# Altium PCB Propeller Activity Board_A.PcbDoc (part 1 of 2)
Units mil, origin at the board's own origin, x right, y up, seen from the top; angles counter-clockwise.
Board outline 4000 x 3050 mil, 4 copper layers (Top Layer, INT1, INT2, Bottom Layer), stack 61.6 mil thick; 104 components, 104 nets, 469 pads, 175 vias.
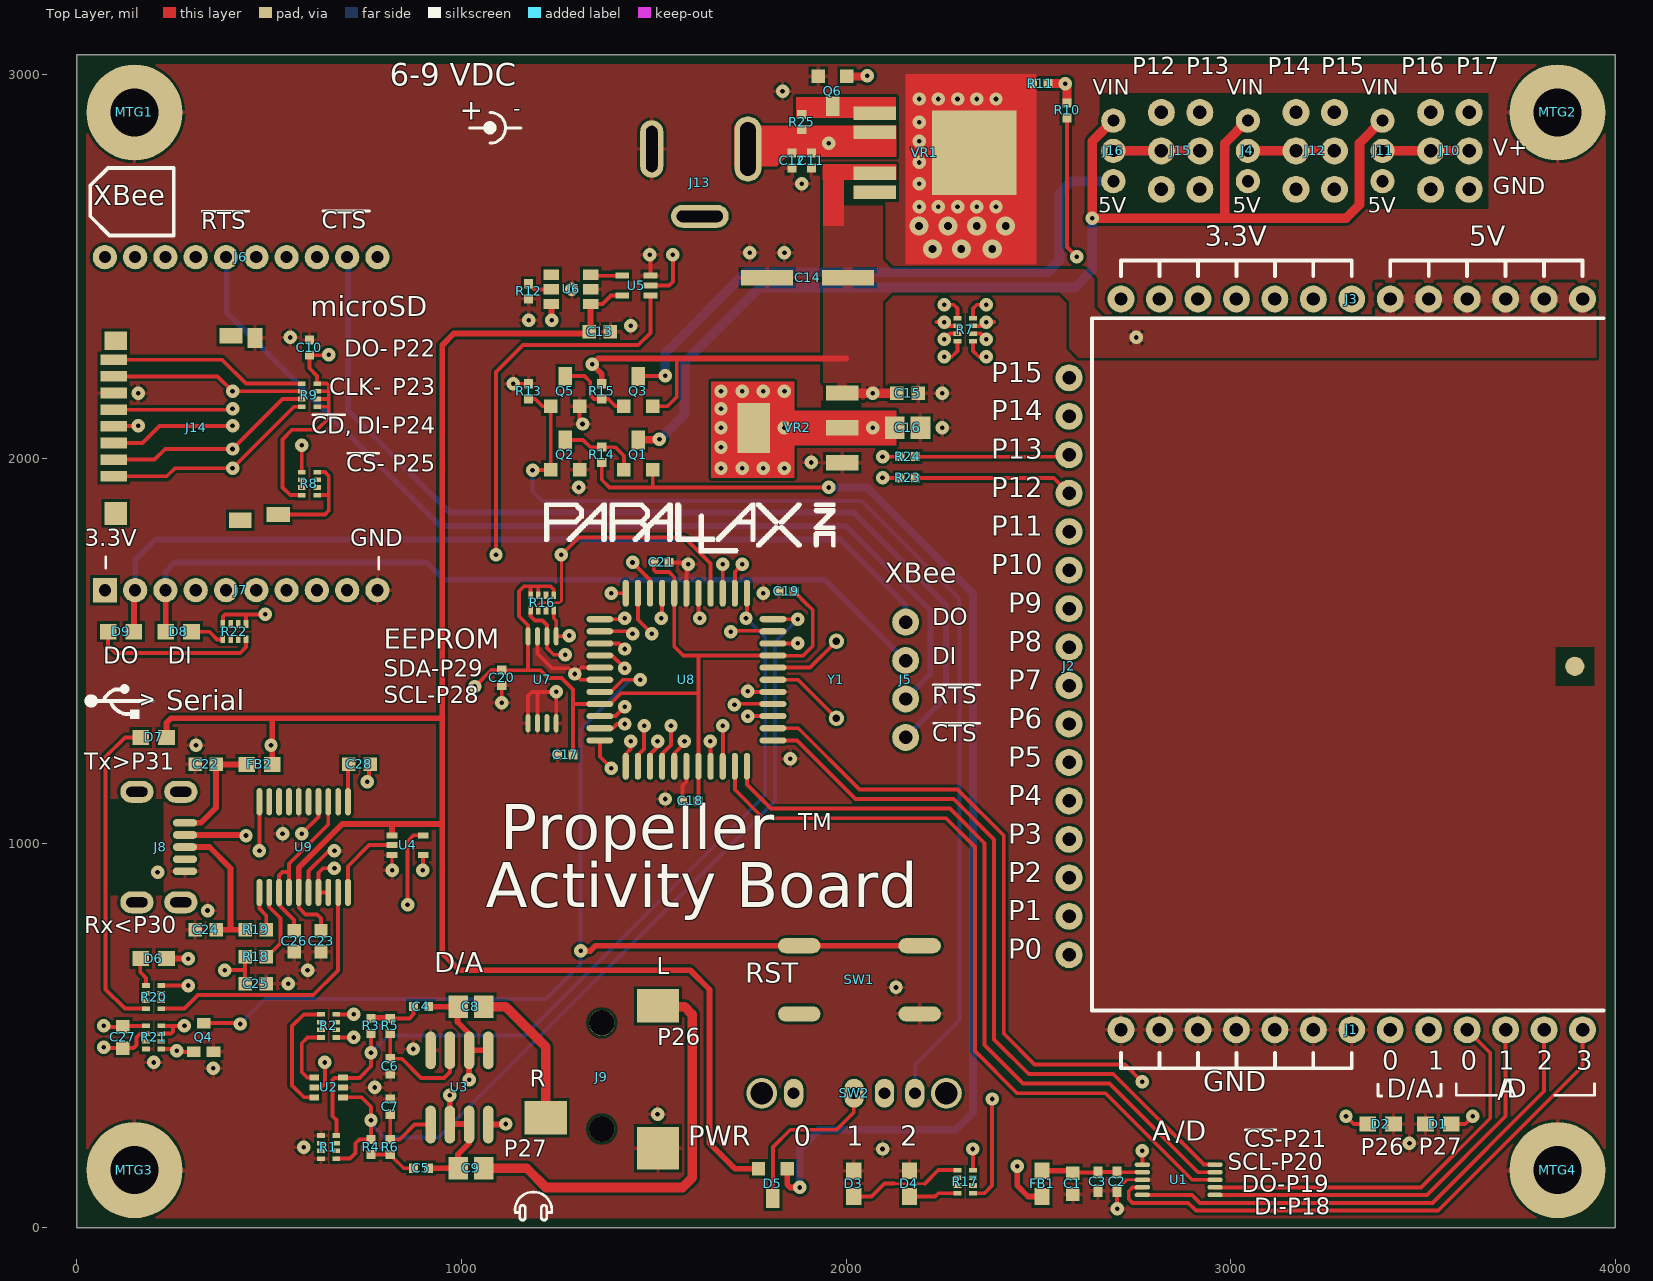
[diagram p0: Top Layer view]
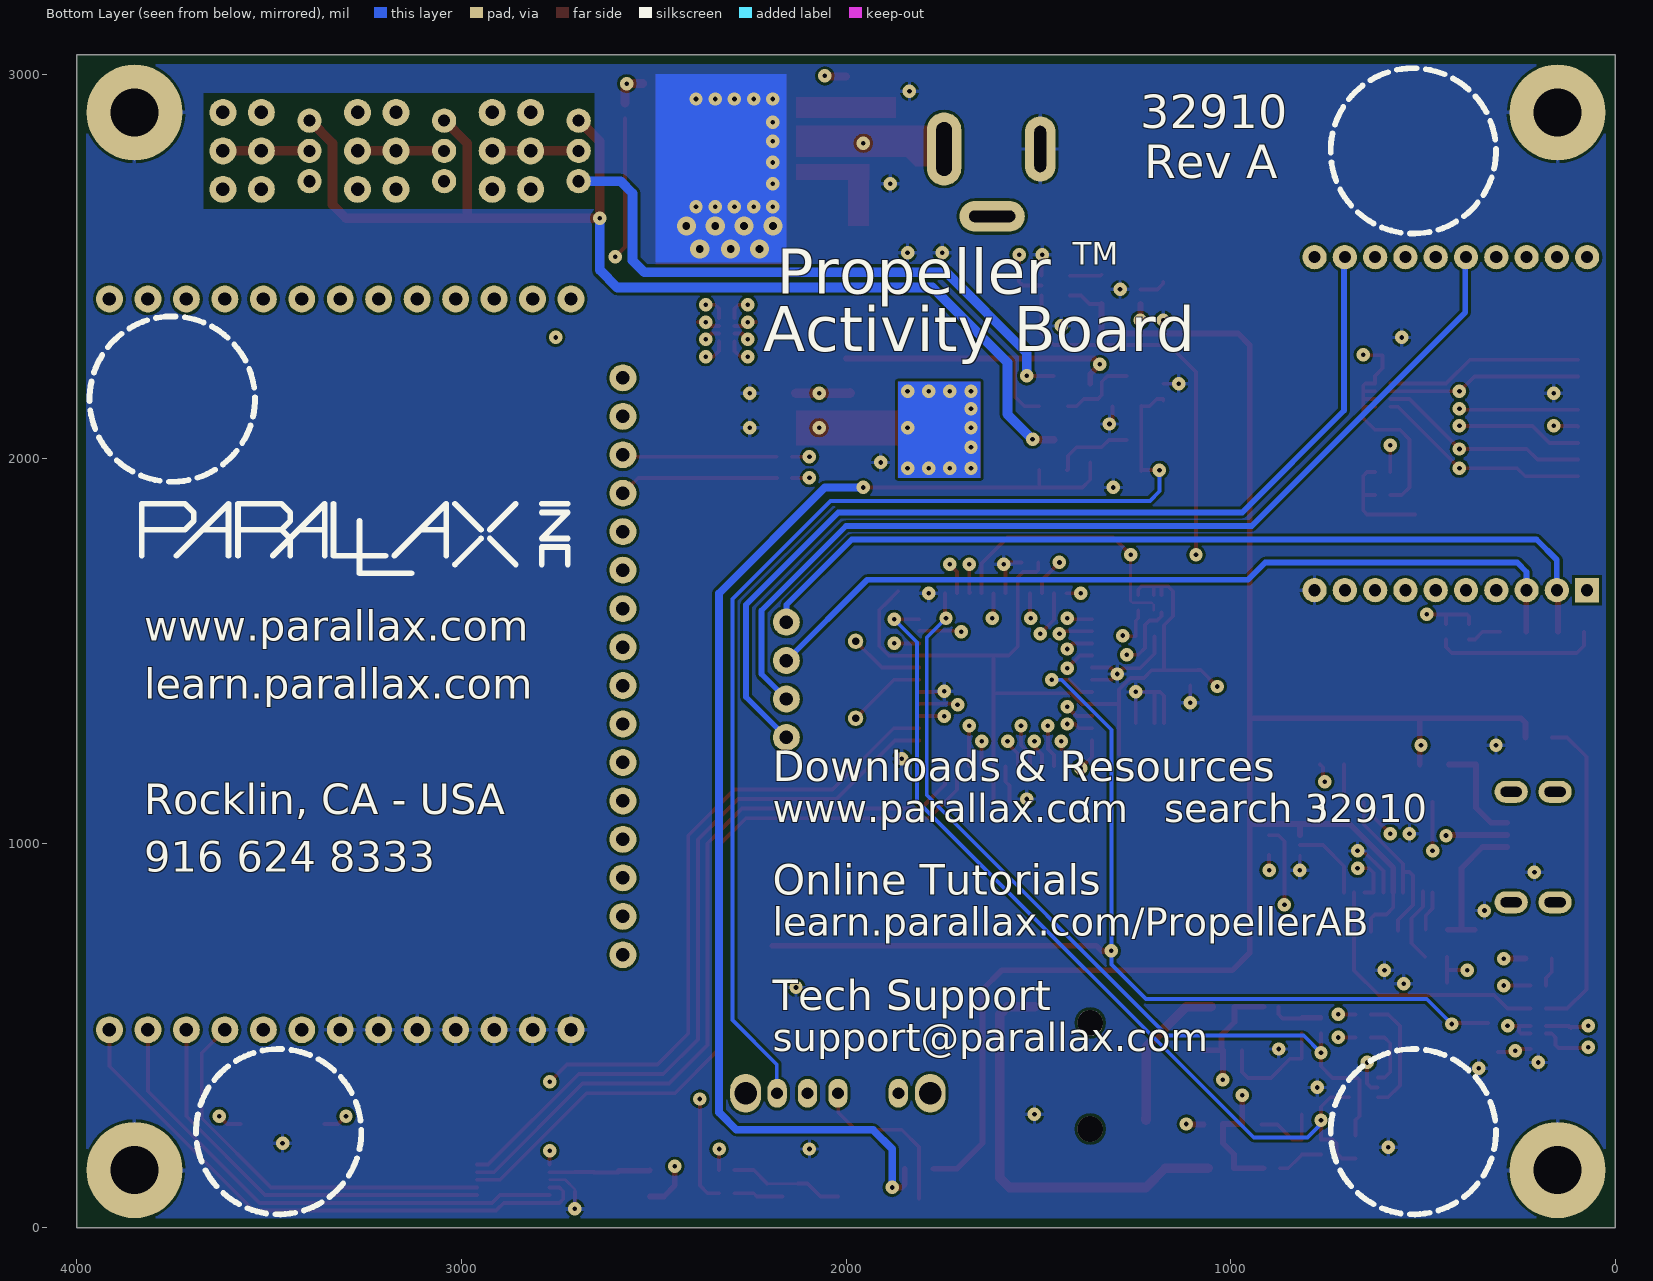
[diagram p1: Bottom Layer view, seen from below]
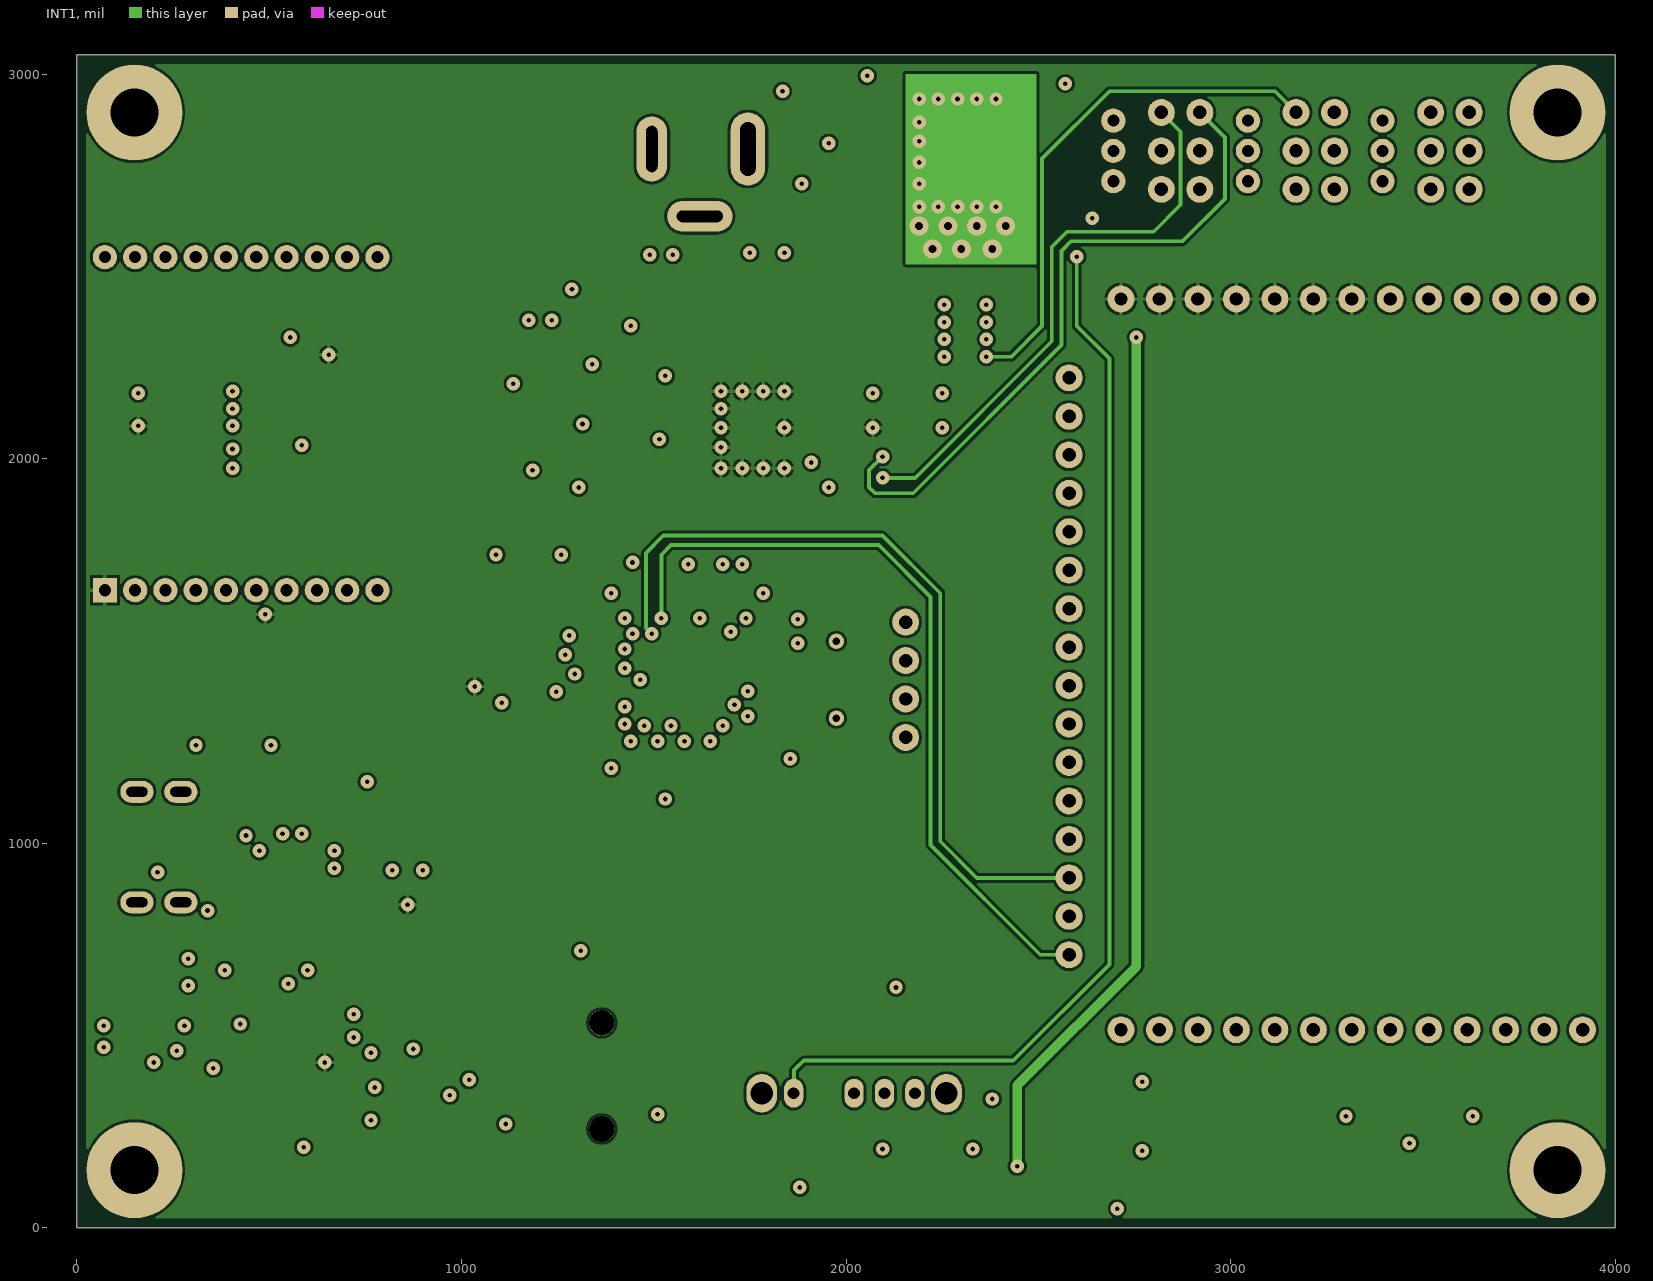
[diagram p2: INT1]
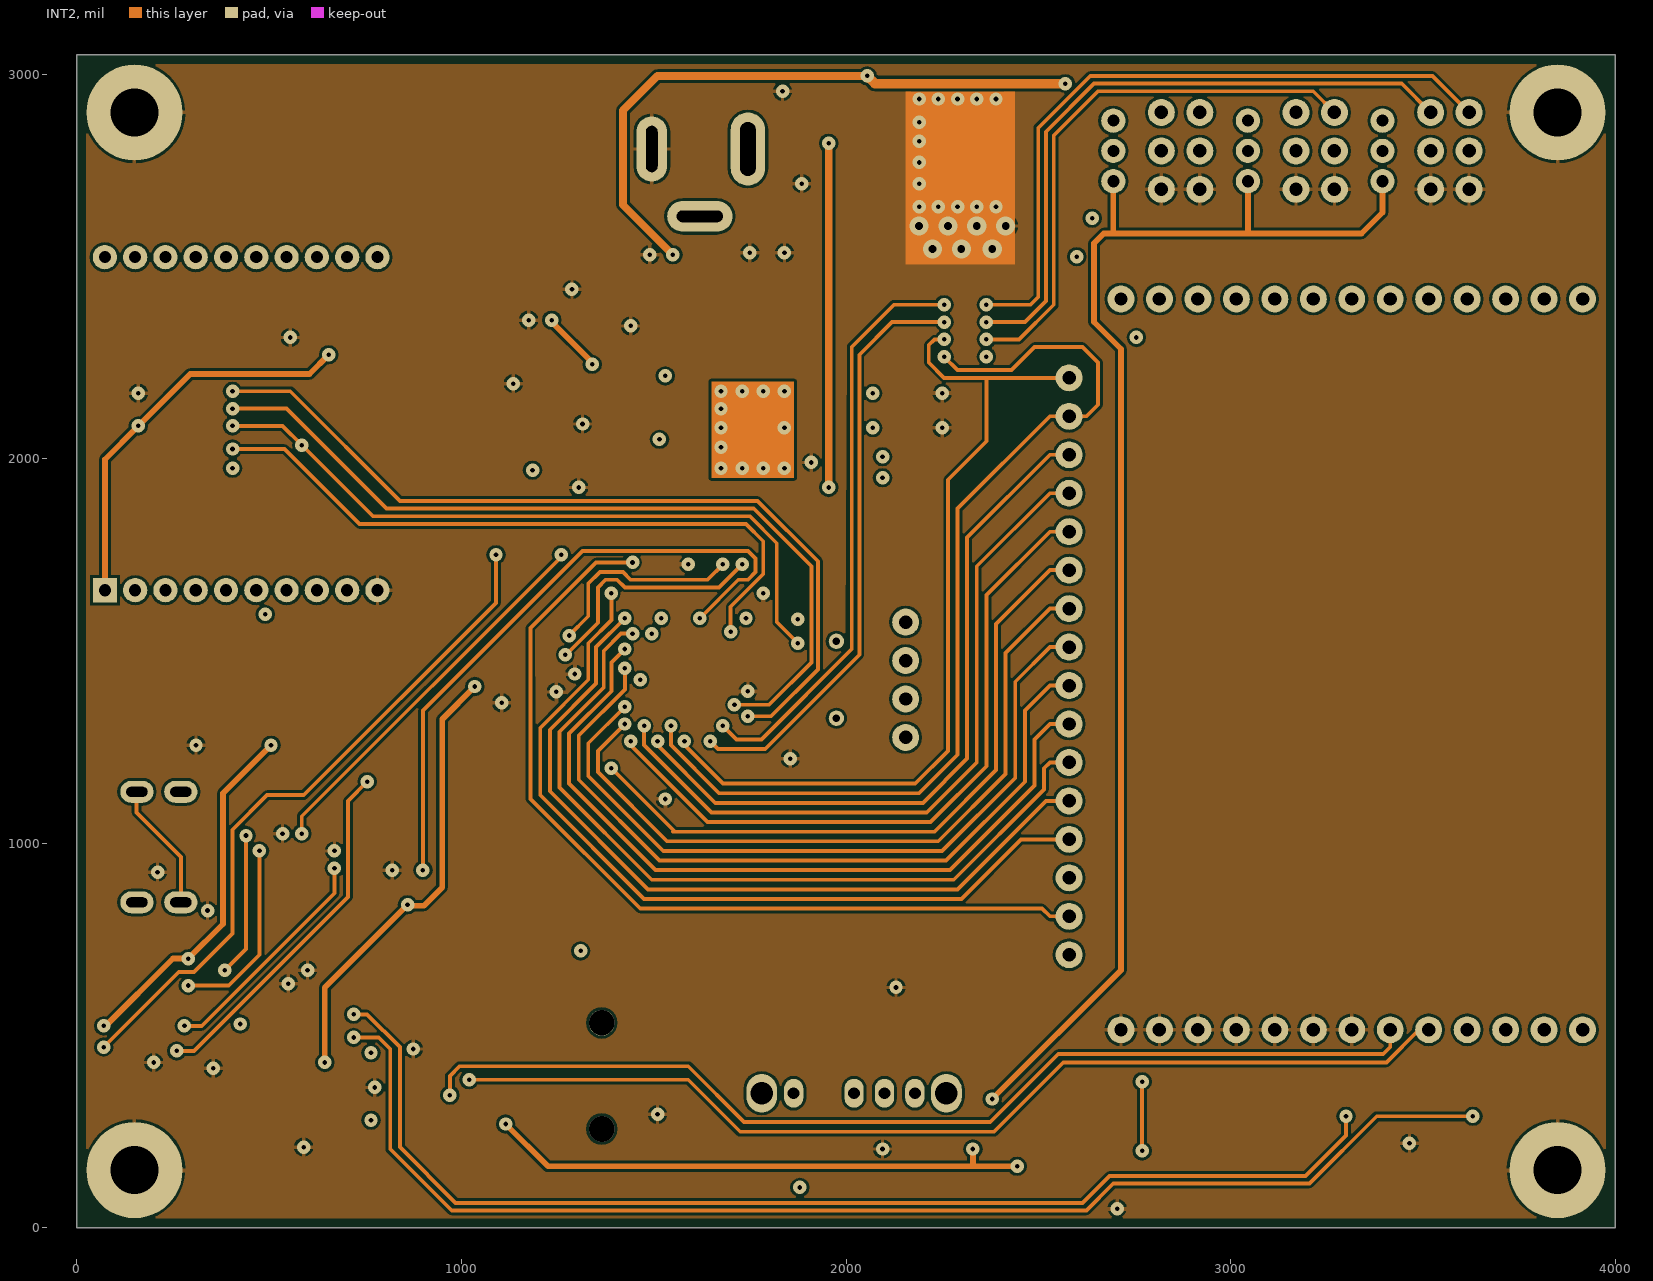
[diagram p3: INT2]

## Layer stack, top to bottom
Top Layer: signal copper 1.4
Dielectric: core 21, FR-4, Dk 4.8
INT1: signal copper 1.4
Dielectric: prepreg 14, FR-4, Dk 4.8
INT2: signal copper 1.4
Dielectric: core 21, FR-4, Dk 4.8
Bottom Layer: signal copper 1.4

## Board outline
0,0 4000,0 4000,3050 0,3050

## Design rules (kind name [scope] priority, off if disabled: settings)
Clearance [All] p1: gap=7
HoleSize [All] p1: absolutevalues=TRUE maxlimit=500 minlimit=1 maxpercent=80.000 minpercent=20.000
MinimumSolderMaskSliver [All] p1: minsoldermaskwidth=0
PlaneConnect "Power Plane Connect Style - from global settings" [All] p1 off: planeconnectstyle=Relief reliefexpansion=20 reliefentries=4 reliefconductorwidth=10 reliefairgap=10
PolygonConnect PolygonConnect_16 [All vs IsNamedPolygon('Top-Layer-5V')] p1: connectstyle=Relief reliefconductorwidth=25 reliefentries=4 polygonreliefangle="90 Angle"
PolygonConnect PolygonConnect_15 [All vs IsNamedPolygon('Top Q1-2')] p2: connectstyle=Direct reliefconductorwidth=10 reliefentries=4 polygonreliefangle="90 Angle"
PolygonConnect PolygonConnect_14 [All vs IsNamedPolygon('Top VIN')] p3: connectstyle=Direct reliefconductorwidth=10 reliefentries=4 polygonreliefangle="90 Angle"
PolygonConnect PolygonConnect_13 [All vs IsNamedPolygon('Top C21-1')] p4: connectstyle=Direct reliefconductorwidth=10 reliefentries=4 polygonreliefangle="90 Angle"
PolygonConnect PolygonConnect_12 [All vs IsNamedPolygon('Top C21-2')] p5: connectstyle=Direct reliefconductorwidth=10 reliefentries=4 polygonreliefangle="90 Angle"
PolygonConnect PolygonConnect_11 [All vs IsNamedPolygon('Top C21-2')] p6: connectstyle=Relief reliefconductorwidth=25 reliefentries=4 polygonreliefangle="90 Angle"
PolygonConnect PolygonConnect_10 [All vs IsNamedPolygon('Top VIN')] p7: connectstyle=Relief reliefconductorwidth=25 reliefentries=4 polygonreliefangle="90 Angle"
PolygonConnect PolygonConnect_9 [All vs IsNamedPolygon('Top C21-2')] p8: connectstyle=Direct reliefconductorwidth=10 reliefentries=4 polygonreliefangle="90 Angle"
PolygonConnect PolygonConnect_8 [All vs IsNamedPolygon('Top C21-2')] p9: connectstyle=Relief reliefconductorwidth=25 reliefentries=4 polygonreliefangle="90 Angle"
PolygonConnect PolygonConnect_7 [All vs IsNamedPolygon('Top C21-2')] p10: connectstyle=Relief reliefconductorwidth=15 reliefentries=4 polygonreliefangle="90 Angle"
PolygonConnect PolygonConnect_6 [All vs IsNamedPolygon('Top C21-2')] p11: connectstyle=Relief reliefconductorwidth=25 reliefentries=4 polygonreliefangle="90 Angle"
PolygonConnect PolygonConnect_5 [All vs IsNamedPolygon('Top VIN')] p12: connectstyle=Relief reliefconductorwidth=25 reliefentries=4 polygonreliefangle="90 Angle"
PolygonConnect PolygonConnect_4 [All vs IsNamedPolygon('Top Q1-2')] p13: connectstyle=Relief reliefconductorwidth=25 reliefentries=4 polygonreliefangle="90 Angle"
PolygonConnect PolygonConnect_3 [All vs IsNamedPolygon('Top C21-1')] p14: connectstyle=Relief reliefconductorwidth=25 reliefentries=4 polygonreliefangle="90 Angle"
PolygonConnect PolygonConnect_2 [All vs IsNamedPolygon('Top C21-2')] p15: connectstyle=Relief reliefconductorwidth=25 reliefentries=4 polygonreliefangle="90 Angle"
PolygonConnect PolygonConnect_1 [All vs IsNamedPolygon('Top VIN')] p16: connectstyle=Relief reliefconductorwidth=25 reliefentries=4 polygonreliefangle="90 Angle"
PolygonConnect [All] p17: connectstyle=Relief reliefconductorwidth=10 reliefentries=4 polygonreliefangle="90 Angle"
RoutingVias [All] p1: holewidth=12 width=35 viastyle="Through Hole" minholewidth=10 minwidth=20 maxholewidth=75 maxwidth=100
SilkToSilkClearance [All] p1 off: silktosilkclearance=1
SilkscreenOverComponentPads [All] p1: minsilkscreentomaskgap=1
SolderMaskExpansion [All] p1: expansion=4
Width [All] p1: maxlimit=100 minlimit=6 preferedwidth=20 midlayer2_minwidth=8 midlayer3_minwidth=8 bottomlayer_minwidth=8 minimp=50.000000 maximp=50.000000 favimp=50.000000
23 further rules are at their usual default settings.

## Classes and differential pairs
component class "Xbee Access Socket": J5
component class "Propeller Activity Board": MTG1 MTG2 MTG3 MTG4
component class "USB Power and Data": C22 C23 C24 C25 C26 C27 C28 D6 D7 FB2 J8 Q4 R18 R19 R20 R21 U4 U9
component class "Power Switch and LEDs": D3 D4 D5 R17 SW1 SW2
component class "Propeller, EEPROM, and Crystal": C17 C18 C19 C20 C21 R16 U7 U8 Y1
component class "Vin Power": C11 C12 C13 C14 C15 C16 J13 Q1 Q2 Q3 Q5 Q6 R10 R11 R12 R13 R14 R15 R25 U5 U6 VR1 VR2
component class "MicroSD Card Socket": C10 J14 R8 R9
component class "Auxiliary Headers": J4 J10 j11 J12 J15 J16 R7 R23 R24
component class "DAC filter, Amp, and Headphones": C4 C5 C6 C7 C8 C9 D1 D2 J9 j11 R1 R2 R3 R4 R5 R6 U2 U3
component class "Breadboard Sockets": J1 J2 J3 P4 P5 P6 P7 P8 P9 P10 P11 P12 P13 P14 P15 P16 P17 P18 P19 P20 P21 P22 P23 P24 P25 P26 P27 P28 P30 P31 P32 P33 P34 P35 P36 P37 P38 P39 P40 P41 P42 P43 P44 P45 P46 P47 P48 P49 P50 P51
component class "XBee Socket": D8 D9 J6 J7 P63 P64 P65 P66 P67 P68 P69 R22
component class ADC: C1 C2 C3 FB1 U1
net class P[0..27]: P0 P1 P2 P3 P4 P5 P6 P7 P8 P9 P10 P11 P12 P13 P14 P15 P16 P17 P18 P19 P20 P21 P22 P23 P24 P25 P26 P27

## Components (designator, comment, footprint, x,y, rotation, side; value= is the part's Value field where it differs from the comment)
C1 "Capacitor" R/C_0603(1608) 2590,115 r270 top
C2 "Capacitor" C_1005N 2705,120 r270 top
C3 "Capacitor" C_1005N 2655,120 r90 top
C4 "Capacitor" R/C_0402(1005) 895,575 r0 top
C5 "Capacitor" R/C_0402(1005) 895,155 r0 top
C6 "Capacitor" R/C_0402(1005) 815,420 r90 top
C7 "Capacitor" R/C_0402(1005) 815,315 r270 top
C8 "Capacitor" R/C_0805(2012) 1025,575 r180 top
C9 "Capacitor" R/C_0805(2012) 1025,155 r0 top
C10 "Capacitor" R/C_0402(1005) 605,2288.62 r90 top
C11 "Capacitor" R/C_0402(1005) 1910,2775 r270 top
C12 "Capacitor" R/C_0402(1005) 1860,2775 r270 top
C13 "Capacitor" R/C_0603(1608) 1360,2330 r0 top
C14 "Cap_Pol" C_6.3x7.7_25V-ALUM 1900,2470 r180 top
C15 "Capacitor" R/C_0603(1608) 2160,2170 r0 top
C16 "Capacitor" R/C_0805(2012) 2160,2080 r180 top
C17 "" R/C_0402(1005) 1270,1230 r0 top
C18 "" R/C_0402(1005) 1595,1110 r0 top
C19 "" R/C_0402(1005) 1845,1655 r0 top
C20 "" R/C_0402(1005) 1105,1430 r90 top
C21 "" R/C_0402(1005) 1520,1730 r180 top
C22 "Capacitor" R/C_0603(1608) 335,1205 r0 top
C23 "Capacitor" R/C_0603(1608) 635,745 r90 top
C24 "Capacitor" R/C_0603(1608) 335,775 r0 top
C25 "Capacitor" R/C_0603(1608) 465,635 r180 top
C26 "Capacitor" R/C_0603(1608) 565,745 r90 top
C27 "" R/C_0603(1608) 120,495 r90 top
C28 "Capacitor" R/C_0603(1608) 735,1205 r180 top
D1 "LED" LED1608-0603#1 3540,270 r180 top
D2 "LED" LED1608-0603#1 3390,270 r0 top
D3 "LED" D_LED1608-0603 2020,115 r90 top
D4 "LED" D_LED1608-0603 2165,115 r90 top
D5 "Diode Pair, CC" Q_SOT23 1810,115 r180 top
D6 "LED" LED1608-0603#2 200,700 r180 top
D7 "LED" LED1608-0603#2 200,1275 r180 top
D8 "LED" D_LED1608-0603 265,1550 r180 top
D9 "LED" D_LED1608-0603 115,1550 r0 top
FB1 "Value: 220 Ohm @ 100MHz, 50 m Ohm DC" CD1608-0603 2510,115 r90 top
FB2 "Ferrite Bead" CD1608-0603 475,1205 r180 top
J1 "Header_1x13" "J_HDR 1X13" 3315,515 r0 top
J2 "Header_1x16" "J_HDR 1X16" 2580,1460 r270 top
J3 "Header_1x13" "J_HDR 1X13" 3315,2415 r0 top
J4 "External Pwr/Cntrl Header" "J_HDR 1X3 2mm" 3045,2800 r270 top
J5 "Header_1x04" "J_HDR 1X4" 2155,1475 r270 top
J6 "Header_1x10" "J_HDR 1X10 2mm"#1 427.39,2523.83 r0 top
J7 "Header_1x10" "J_HDR 1X10 2mm"#2 427.39,1657.83 r0 top
J8 "USB_MiniB" "J_USB MINI B-TH_SD-51387-3" 120,990 r90 top
J9 "Phonejack" "CON-JACK-AUDIO 3.5MM" 1365,395 r90 top
J10 "Headers for selection jumpers" "J_HDR 2X3" 3570,2800 r270 top
J11 "External Pwr/Cntrl Header" "J_HDR 1X3 2mm" 3395,2800 r270 top
J12 "Headers for selection jumpers" "J_HDR 2X3" 3220,2800 r270 top
J13 "PWR2.1" "J_CON 2.1mm PWR" 1495,2805 r90 top
J14 "microSD" J_SCKT_DM3D-SF 310,2085 r270 top
J15 "Headers for selection jumpers" "J_HDR 2X3" 2870,2800 r270 top
J16 "External Pwr/Cntrl Header" "J_HDR 1X3 2mm" 2695,2800 r270 top
MTG1 "Screw Hole" MTG_250R-125D#1 150,2900 r0 top
MTG2 "Screw Hole" MTG_250R-125D#1 3850,2900 r0 top
MTG3 "Screw Hole" MTG_250R-125D#2 175,150 r0 top
MTG4 "Screw Hole" MTG_250R-125D#1 3850,150 r0 top
Q1 "D" Q_SOT23 1460,2010 r0 top
Q2 "D" Q_SOT23 1270,2010 r0 top
Q3 "D" Q_SOT23 1460,2175 r0 top
Q4 "BJT_NPN" Q_SOT323 330,495 r0 top
Q5 "D" Q_SOT23 1270,2175 r0 top
Q6 "MOSFET_BSS123" Q_SOT23 1965,2955 r180 top
R1 "Res_Net" R_ARRAY-0402x4 655,210 r180 top
R2 "Res_Net" R_ARRAY-0402x4 655,525 r180 top
R3 "Resistor" R/C_0402(1005) 765,525 r270 top
R4 "Resistor" R/C_0402(1005) 765,210 r90 top
R5 "Resistor" R/C_0402(1005) 815,525 r90 top
R6 "Resistor" R/C_0402(1005) 815,210 r270 top
R7 "Res_Net" R_ARRAY-0402X4 2310,2335 r0 top
R8 "Res_Net" R_ARRAY-0402x4 605,1935 r180 top
R9 "Res_Net" R_ARRAY-0402x4 605,2165 r180 top
R10 "Resistor" R/C_0402(1005) 2575,2905.32 r270 top
R11 "Resistor" R/C_0402(1005) 2505,2975 r0 top
R12 "Resistor" R/C_0402(1005) 1175,2435 r90 top
R13 "Resistor" R/C_0402(1005) 1175,2175 r270 top
R14 "Resistor" R/C_0402(1005) 1365,2010 r90 top
R15 "Resistor" R/C_0402(1005) 1365,2175 r90 top
R16 "Res_Net" R_ARRAY-0402x4 1210,1625 r270 top
R17 "Res_Net" R_ARRAY-0402x4 2310,120 r180 top
R18 "Resistor" R/C_0603(1608) 465,705 r180 top
R19 "Resistor" R/C_0603(1608) 465,775 r180 top
R20 "Res_Net" R_ARRAY-0402x4 200,600 r180 top
R21 "Res_Net" R_ARRAY-0402x4 200,495 r180 top
R22 "Res_Net" R_ARRAY-0402x4 410,1550 r90 top
R23 "Resistor" R/C_0402(1005) 2160,1950 r180 top
R24 "Resistor" R/C_0402(1005) 2160,2005 r180 top
R25 "Resistor" R/C_0402(1005) 1885,2875 r90 top
SW1 "SW-PB" SW_SMD_J-bend 2035,645 r0 top
SW2 "Power selection switch" SWI_OS103011MS8QP1 2021,350 r0 top
U1 "ADC124S021" U_MSSOP10 2865,125 r0 top
U2 "NC7WZ17" SOT363-6L 655,365 r180 top
U3 "TSV912" SOIC127P600-8M 995,365 r270 top
U4 "74LVC1G126" SOT353-5AN 860,995 r0 top
U5 "74LVC1G32" SOT323-5L 1455,2450 r180 top
U6 "TPS2552DBV" U_TPS2553DBVT 1285,2440 r180 top
U7 "AT24C512" U_AT24C512K 1210,1425 r90 top
U8 "P8X32A" U_P8X32A-Q44 1585,1425 r0 top
U9 "FT231X" U_SSOP20_FT231XS 590,990 r270 top
VR1 "LD29150PT50R" VR_PPAK 2190,2795 r270 top
VR2 "AP1117-3.3" VR_SOT223 1875,2080 r90 top
Y1 "XTAL" Y_HC-49US 1975,1425 r0 top

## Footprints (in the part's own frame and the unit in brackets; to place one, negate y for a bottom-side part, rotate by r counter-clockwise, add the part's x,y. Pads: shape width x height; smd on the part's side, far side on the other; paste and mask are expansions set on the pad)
C_6.3x7.7_25V-ALUM [mil]
  rect 135x40 smd: 1(-105,0) 2(105,0)
C_1005N [mm]
  rect 0.8x0.6 smd: 1(-0.6,0) 2(0.6,0)
  body extent -0.55,-0.3 0.55,0.3, height 0.6
CD1608-0603 [mm]
  rect 1.1x1 smd: 1(-0.85,0) 2(0.85,0)
  body extent -1.5,-0.6 1.5,0.6, height 0.76
"CON-JACK-AUDIO 3.5MM" [mil]
  rect 110x110 smd: 1(-188,-146)
  rect 87x110 smd: 2(182,-146) 3(-109,146)
  round 67 hole 67 unplated: 4(-138,0) 5(138,0)
D_LED1608-0603 [mm]
  rect 1.1x1 smd: 1(-0.85,0) 2(0.85,0)
"J_CON 2.1mm PWR" [mil]
  oval 170x70 / inner oval 190x90 / far side oval 190x90 hole 40 slot 140 at 0 deg mask+5: +(0,-250)
  oval 150x60 / inner oval 170x80 / far side oval 170x80 hole 30 slot 120 at 0 deg mask+5: -(0,0)
  oval 60x150 / inner oval 80x170 / far side oval 80x170 hole 30 slot 120 at 90 deg mask+5: S(-175,-125)
"J_HDR 1X3 2mm" [mm] "CON-HDR_1X3"
  round 1.6 hole 0.8 mask+0.127: 1(-2,0) 2(0,0) 3(2,0)
  body extent -3.09,-1.09 3.09,1.09, height 3.81
"J_HDR 1X4" [mil] "CON-HDR_1X4"
  round 70 hole 35 mask+5: 1(-100,0) 2(0,0) 3(100,0) 4(200,0)
"J_HDR 1X10 2mm"#1 [mm] "CON-HDR_1X10"
  round 1.6 hole 0.8: 1(-9,0) 2(-7,0) 3(-5,0) 4(-3,0) 5(-1,0) 6(1,0) 7(3,0) 8(5,0) 9(7,0) 10(9,0)
"J_HDR 1X10 2mm"#2 [mm] "CON-HDR_1X10"
  rect 1.6x1.6 hole 0.8: 1(-9,0)
  round 1.6 hole 0.8: 2(-7,0) 3(-5,0) 4(-3,0) 5(-1,0) 6(1,0) 7(3,0) 8(5,0) 9(7,0) 10(9,0)
"J_HDR 1X13" [mil] "CON-HDR_1X13"
  round 70 hole 35 mask+5: 1(-600,0) 2(-500,0) 3(-400,0) 4(-300,0) 5(-200,0) 6(-100,0) 7(0,0) 8(100,0) 9(200,0) 10(300,0) 11(400,0) 12(500,0) 13(600,0)
"J_HDR 1X16" [mil] "CON-HDR_1X16"
  round 70 hole 35 mask+5: 1(-750,0) 2(-650,0) 3(-550,0) 4(-450,0) 5(-350,0) 6(-250,0) 7(-150,0) 8(-50,0) 9(50,0) 10(150,0) 11(250,0) 12(350,0) 13(450,0) 14(550,0) 15(650,0) 16(750,0)
"J_HDR 2X3" [mil] "CON-HDR_2X3"
  round 70 hole 35 mask+5: 1(-100,-50) 2(-100,50) 3(0,-50) 4(0,50) 5(100,-50) 6(100,50)
J_SCKT_DM3D-SF [mm] "Micro SD Card"
  rect 0.7x1.75 smd mask+0.125: 1(3.327,-5.42) 2(2.227,-5.42) 3(1.127,-5.42) 4(0.027,-5.42) 5(-1.073,-5.42) 6(-2.173,-5.42) 7(-3.273,-5.42) 8(-4.373,-5.42)
  rect 1.25x1.5 smd mask+0.127: 9(-5.623,-5.295)
  rect 1.5x1.5 smd mask+0.127: 10(5.777,-5.295)
  rect 1.029x1.5 smd mask+0.076: 11(-5.969,2.305) 12(6.223,2.93)
  rect 1.321x1 smd mask+0.076: 13(-5.817,3.896)
  rect 1x1.55 smd mask+0.127: 14(5.842,5.42)
"J_USB MINI B-TH_SD-51387-3" [mm]
  oval 0.508x1.6 smd mask+0.127: 1(-1.6,-4.1) 2(-0.8,-4.1) 3(0,-4.1) 4(0.8,-4.1) 5(1.6,-4.1)
  oval 1.45x2.2 hole 0.65 slot 1.4 at 90 deg mask+0.127: 6(3.65,-3.825) 7(-3.65,-3.825) 8(3.65,-0.925) 9(-3.65,-0.925)
  Top Layer pour cut-out: 3.175,-2.667 -3.175,-2.667 -3.175,0.978 3.175,0.978
LED1608-0603#1 [mm]
  rect 1.1x1 smd: 1(-0.85,0) 2(0.85,0)
LED1608-0603#2 [mm]
  rect 1.1x1 smd: A(-0.85,0) K(0.85,0)
MTG_250R-125D#1 [mil] "4-40 Mounting Hole"
  round 250 hole 125 mask+5: 1(0,0)
MTG_250R-125D#2 [mil] "4-40 Mounting Hole"
  round 250 hole 125 mask+5: 1(-25,0)
Q_SOT23 [mil] "XSTR"
  rect 35x35 smd mask+5: 1(-37.5,-38.75) 2(37.5,-38.75)
  rect 35x50 smd mask+5: 3(0,38.75)
Q_SOT323 [mm] "XSTR"
  rect 0.9x0.7 smd mask+0.127: 1(-0.65,-0.95) 2(0.65,-0.95) 3(0,0.95)
R/C_0402(1005) [mm] "Standard 0402 footprint used for Resistors and Capacitors"
  rect 0.6x0.6 smd: 1(-0.5,0) 2(0.5,0)
  body extent -0.55,-0.3 0.55,0.3, height 0.6
R/C_0603(1608) [mil] "Standard 0603 footprint used for Resistors and Capacitors"
  rect 35x35 smd: 1(-27.5,0) 2(27.5,0)
R/C_0805(2012) [mm] "Standard 0805 footprint used for Resistors and Capacitors"
  rect 1.3x1.5 smd: 1(-0.85,0) 2(0.85,0)
  body extent -1.1,-0.72 1.1,0.72, height 1.1
R_ARRAY-0402x4 [mil] "741X083103JP"
  rect 20x12 smd mask+3: 1(-20,30) 2(-20,10) 3(-20,-10) 4(-20,-30) 5(20,-30) 6(20,-10) 7(20,10) 8(20,30)
R_ARRAY-0402X4 [mil] "741X083103JP"
  rect 20x12 smd mask+3: 1(-20,30) 2(-20,10) 3(-20,-10) 4(-20,-30) 5(20,-30) 6(20,-10) 7(20,10) 8(20,30)
SOIC127P600-8M [mm]
  oval 2.5x0.7 smd: 1(-2.45,1.905) 2(-2.45,0.635) 3(-2.45,-0.635) 4(-2.45,-1.905) 5(2.45,-1.905) 6(2.45,-0.635) 7(2.45,0.635) 8(2.45,1.905)
  body extent -2,-2.5 2,2.5, height 1.75
SOT323-5L [mm]
  rect 0.9x0.4 smd: 1(-0.93,0.65) 2(-0.93,0) 3(-0.93,-0.65) 4(0.93,-0.65) 5(0.93,0.65)
SOT353-5AN [mm]
  rect 0.7x0.4 smd: 1(-1.025,0.65) 2(-1.025,0) 3(-1.025,-0.65) 4(1.025,-0.65) 5(1.025,0.65)
  body extent -0.7,-1.1 0.7,1.1, height 1.1
SOT363-6L [mm]
  rect 0.65x0.4 smd: 1(-0.95,0.65) 2(-0.95,0) 3(-0.95,-0.65) 4(0.95,-0.65) 5(0.95,0) 6(0.95,0.65)
  body extent -0.7,-1.1 0.7,1.1, height 1
SW_SMD_J-bend [mm] "6mm Tact Switch"
  oval 2.8x1 smd: 1(-3.975,2.25) 1(3.975,2.25) 2(-3.975,-2.25) 2(3.975,-2.25)
SWI_OS103011MS8QP1 [mil] "Switch SP3T"
  oval 50x75 hole 31: 1(-157,0) 2(0,0) 3(79,0) 4(158,0)
  round 80 / inner oval 80x100 / far side oval 80x100 hole 59: 5(240,0) 6(-240,0)
U_AT24C512K [mm] "IC_EEPROM"
  oval 1.2x0.33 smd mask+0.076: 1(-2.87,0.93) 2(-2.87,0.31) 3(-2.87,-0.31) 4(-2.87,-0.93) 5(2.87,-0.93) 6(2.87,-0.31) 7(2.87,0.31) 8(2.87,0.93)
U_MSSOP10 [mil] "IC_ADC124S021"
  oval 40x12 smd: 1(-94.5,39.4) 2(-94.5,19.7) 3(-94.5,0) 4(-94.5,-19.7) 5(-94.5,-39.4) 6(94.5,-39.4) 7(94.5,-19.7) 8(94.5,0) 9(94.5,19.7) 10(94.5,39.4)
  body extent -60,-60 60,60, height 69
U_P8X32A-Q44 [mil] "Propeller-Microprocessor"
  oval 70x16 smd mask+3: 1(-225,157.5) 2(-225,126) 3(-225,94.5) 4(-225,63) 5(-225,31.5) 6(-225,0) 7(-225,-31.5) 8(-225,-63) 9(-225,-94.5) 10(-225,-126) 11(-225,-157.5) 23(225,-157.5) 24(225,-126) 25(225,-94.5) 26(225,-63) 27(225,-31.5) 28(225,0) 29(225,31.5) 30(225,63) 31(225,94.5) 32(225,126) 33(225,157.5)
  oval 16x70 smd mask+3: 12(-157.5,-225) 13(-126,-225) 14(-94.5,-225) 15(-63,-225) 16(-31.5,-225) 17(0,-225) 18(31.5,-225) 19(63,-225) 20(94.5,-225) 21(126,-225) 22(157.5,-225) 34(157.5,225) 35(126,225) 36(94.5,225) 37(63,225) 38(31.5,225) 39(0,225) 40(-31.5,225) 41(-63,225) 42(-94.5,225) 43(-126,225) 44(-157.5,225)
  body extent -194,-194 194,194, height 65
U_SSOP20_FT231XS [mm]
  oval 1.8x0.38 smd: 1(-2.992,2.925) 2(-2.992,2.275) 3(-2.992,1.625) 4(-2.992,0.975) 5(-2.992,0.325) 6(-2.992,-0.325) 7(-2.992,-0.975) 8(-2.992,-1.625) 9(-2.992,-2.275) 10(-2.992,-2.925) 11(2.992,-2.925) 12(2.992,-2.275) 13(2.992,-1.625) 14(2.992,-0.975) 15(2.992,-0.325) 16(2.992,0.325) 17(2.992,0.975) 18(2.992,1.625) 19(2.992,2.275) 20(2.992,2.925)
U_TPS2553DBVT [mil] "IC_SOT23-6"
  rect 40x27 smd: 1(-51,38) 2(-51,0) 3(-51,-38) 4(51,-38) 5(51,0) 6(51,38)
VR_PPAK [mil] "LD29150 Voltage Regulator"
  rect 35x110 smd: 1(-103,-115) 2(-53,-115) 4(53,-115) 5(103,-115)
  rect 220x220 smd paste-393.7: 3(0,143.7)
VR_SOT223 [mil] "Voltage Regulator"
  rect 40x85 smd: 1(-90.5,-115) 2(0,-115) 3(90.5,-115)
  rect 130x85 smd: 4(0,115)
Y_HC-49US [mil] "ECS 50-20-4 CRYSTAL"
  round 40 hole 20 mask+5: 1(0,-100) 2(0,100)

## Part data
C10: "Standard Filter Cap"
C14: "Polarized Capacitor"
C17 C18 C19 C20 C21: library part Capacitor, "Cap, 1uF, 0402, X5R"
C27: library part Capacitor
D5: library part Diode_Pair_CC, "Diode Pair, Common Cathode"
FB1: library part "Ferrite Bead"
J1 J3: "Header, 13-Pin"
J2: "Header, 16-Pin"
J4 J11 J16: library part Header_1x03, "Header, 1x3, Straight, 0.1\""
J5: "Header, 1x4, Straight, 0.1\""
J6 J7: "Header, 10-Pin"
J8: "USB Mini B"
J9: "Jack Socket, 1/8\" [6.5mm], Thru-Hole, Vertical, 3-Conductor Open Circuit (Non-Normalling)"
J10 J12 J15: library part Header_2x03, "Header, 2x3, Straight, 0.1\""
J13: "Low Voltage Power Supply Connector"
J14: library part DM3D-SF
MTG1 MTG2 MTG3 MTG4: library part Screw_Hole, "Screw hole for mounting (or high-current connection)"
Q1 Q3: library part MOSFET-P, "MOSFET P-ch"
Q2 Q5: library part MOSFET-N, "MOSFET N-ch"
Q4: "NPN Bipolar Transistor"
Q6: library part "MOSFET-N DUAL", "BSS123"
R1 R2 R7 R8 R9 R16 R17 R20 R21 R22: "Resistor Network"
SW1: "Push-button switch"
SW2: library part SW-SP3T, "Switch SP3T"
U1: library part U_ADC124S021
U2: "2-bit Schmitt Trigger Buffer"
U3: library part LMV358, "Rail-to-Rail Ap-Amp, 2.7 to 5.5 V, 1 MHZ GBWP"
U4: "1-bit Buffer with Enable, Non-inv"
U5: "OR gate"
U6: library part TPS2552DBVR, "Current-limited Power-distribution Switch"
U7: "512K (65,536 x 8) I2C EEPROM"
U8: library part P8X32A-Q44
U9: "USB UART"
VR1: library part VR_LD29150, "VR_LD29150"
VR2: "3.3V 1A LDO"
Y1: "Crystal Oscillator"

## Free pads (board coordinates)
  round 50 smd paste-50: 2(3895,1460)

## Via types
v1: diameter 35, hole 12, Top Layer to Bottom Layer, tented both sides, 168 vias
v2: diameter 50, hole 20, Top Layer to Bottom Layer, tented both sides, 7 vias

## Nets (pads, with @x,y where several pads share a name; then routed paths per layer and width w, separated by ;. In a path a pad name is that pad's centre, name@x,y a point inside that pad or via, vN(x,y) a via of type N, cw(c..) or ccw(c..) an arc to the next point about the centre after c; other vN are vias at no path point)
3.3V: C10.1 C16.2 C17.2 C18.2 C19.2 C20.2 C21.2 J3.1 J3.2 J3.3 J3.4 J3.5 J3.6 J3.7 J7.1 J14.4 R8.8 R9.1 R9.2 R9.3 R9.4 R16.1 R16.3 R16.4 R22.5 R22.8 U2.5 U4.5 U7.8 U8.8 U8.18 U8.30 U8.40 VR2.2 VR2.4 | length 5741.2
  Top Layer w10: J14.4@96.61,2083.94 97.68,2085 v1(160,2085) ; R22.8@380,1570 380,1590 385,1595 440,1595 ; R22.5@440,1570 440,1595 ; v1(490,1595) 440,1595 ; R8.8@585,1905 555,1905 535,1925 535,2050 560,2075 625,2075 655,2105 655,2135 ; U2.5@617.6,365 635,365 645,375 v1(645,430) ; R9.1@625,2135 655,2135 ; R9.2@625,2155 655,2155 ; R9.3@625,2175 655,2175 ; v1(655,2270) 653.94,2268.94 C10.1@605,2268.94 605,2235 625,2215 R9.4@625,2195 650,2195 655,2190 655,2175 ; v1(860,840) 860,1005 875.59,1020.59 U4.5@900.35,1020.59 ; v1(1035,1407.5) 1077.5,1450 1085,1450 ; 1085,1449.68 C20.2@1105,1449.68 1173.39,1449.68 ; R16.4@1180,1645 1180,1668 ; R16.3@1200,1645 1200,1665 ; R16.1@1240,1645 1240,1660 1232,1668 1180,1668 ; C17.2@1290,1230 1290,1362 ; C21.2@1500.32,1730 1500.32,1710.32 1505.63,1705 1540,1705 1553.5,1691.5 U8.40@1553.5,1650 1553.5,1511.5 1577,1488 U8.30@1810,1488 ; 1615,1390 1415,1390 1387,1362 U8.8@1360,1362 1290,1362 ; 1616.5,1486.5 U8.18@1616.5,1200 1616.5,1110 C18.2@1620,1106.5 ; U8.30@1810.5,1487.5 1888.46,1487.5 1913.46,1512.5 1913.46,1606.54 1900,1620 ; C19.2@1864.68,1655 1899.84,1619.84 ; 655,2135 655,2155 ; 655,2155 655,2175 ; 1173.39,1449.68 U7.8@1173.39,1538 1173.39,1566.61 1150,1590 1150,1655 1163,1668 1180,1668 ; 1173.39,1449.68 1205.32,1449.68 1225,1430 1260,1430 1290,1400 1290,1362
  INT2 w15: J7.1@73.06,1657.83 73.06,1998.06 v1(160,2085) 295,2220 605,2220 v1(655,2270) ; v1(645,430) 645,625 857.5,837.5 902.5,837.5 950,885 950,1322.5 v1(1035,1407.5)
  other v1: 1675,1975 1730,1975 1785,1975 1840,1975 1675,2030 1675,2080 1840,2080 2070,2080 1675,2130 1675,2175 1730,2175 1785,2175 1840,2175
5V: C14.1 C15.1 FB1.1 J3.8 J3.9 J3.10 J3.11 J3.12 J3.13 Q3.2 R15.2 R17.4 U3.8 U6.6 VR1.4 VR2.3 | length 5169.2
  Top Layer w10: Q3.2@1497.5,2136.25 1536.25,2136.25 1560,2160 1560,2260 ; R17.4@2330,150 v1(2330,205)
  Top Layer w15: U3.8@1070,268.54 v1@1113.54,268.54 ; v1@1234,2361 U6.6@1234,2402 ; R15.2@1365,2194.68 1365,2220 v1(1340,2245) 1355,2260 1560,2260 2000,2260 ; v1(2445,160) 2445,110 2473.46,81.54 FB1.1@2510,81.54
  Top Layer w25: VR2.3@1990,2170.5 1989.5,2170 v1(2070,2170) C15.1@2130,2170
  INT1 w25: v1(2445,160) 2445,370 2755,680 v1(2755,2315)
  INT2 w15: v1(1115,270) 1225,160 2330,160 ; v1(1235,2360) 1235,2355 1340,2250 v1(1340,2245) ; v1(2330,205) 2330,160 ; v1(2445,160) 2330,160
5V_AN: C1.1 C2.1 C3.2 FB1.2 U1.2 | length 261.8
  Top Layer w10: C1.1@2590,145 2591.38,143.62 C3.2@2655,143.62 ; C3.2@2655,145 2705,145 2705.3,144.7 U1.2@2770.5,144.7
  Top Layer w15: FB1.2@2510,150 2511.54,148.46 C1.1@2590,148.46
5V_AUX: J4.3 J11.3 J16.3 Q3.3 R17.1 | length 5394.6
  Top Layer w10: Q3.3@1460,2215 v1(1530,2215) ; R17.1@2330,90 2360,90 2380,110 v1(2380,335)
  INT2 w15: v1@2382.5,337.5 2715,670 2715,2285 2645,2355 2645,2560 2670,2585 2695,2585 ; J16.3@2695,2725 2695,2585 ; J4.3@3045,2720 3045,2585 ; J11.3@3395,2720 3395,2640 3340,2585 3045,2585 ; 2695,2585 3045,2585
  Bottom Layer w25: v1(1530,2215) 1530,2275 1740,2485 2525,2485 2555,2515 2555,2690 2586.26,2721.26 2691.26,2721.26 J16.3@2695,2725
5V_USB: C13.1 C23.2 C27.2 D5.2 D6.A D7.A FB2.1 R21.5 U4.1 U5.5 U6.1 U9.15 | length 6086.3
  Top Layer w10: v1(70,525) 72.5,522.5 C27.2@120,522.5 ; C27.2@114.68,520 C27.2@114.84,519.84 ; C27.2@120,525 R21.5@180,525 ; U9.15@577.2,872.2 577.2,832.8 595,815 625,815 635,805 C23.2@635,772.5 C23.2@635,770 ; U6.1@1336,2402 1367,2402 1389.41,2424.41 U5.5@1418.39,2424.41
  Top Layer w15: D6.A@233.46,700 v1(290,700) ; D7.A@233.46,1275 233.46,1313.46 245,1325 950,1325 ; FB2.1@508.46,1205 508.46,1323.46 ; U9.15@577.2,872.2 577.2,937.2 690,1050 950,1050 ; U4.1@819.65,1020.59 819.65,1049.65 ; C13.1@1335,2325 980,2325 950,2295 950,715 995,670 1595,670 1645,620 1645,220 1711.25,153.75 D5.2@1772.5,153.75 ; C13.1@1336,2321 U6.1@1336,2402
  INT2 w15: v1(70,525) 70,520 250,700 v1(290,700) 380,790 380,1130 v1(505,1255)
A\U\X\_\E\N\: Q2.1 Q5.1 R13.2 SW2.4 | length 2902.5
  Top Layer w10: R13.2@1175,2151.38 R13.2@1178.62,2155 ; R13.2@1175,2155 1192,2155 1210.75,2136.25 Q5.1@1232.5,2136.25 ; v1(1185,1970) 1230,1970 1232.5,1967.5 Q2.1@1232.5,1971.25 Q5.1@1232.5,2136.25 ; Q5.1@1232.5,2137.5 Q5.1@1232.5,2136.25
  Bottom Layer w10: v1(1185,1970) 1185,1915 1210,1890 2040,1890 2295,1635 2295,540 2180,425 SW2.4@2180,350
AD0: J1.10 U1.7 | length 1044.8
  Top Layer w10: U1.7@2959.5,105.3 3495.3,105.3 3675,285 3675,455 J1.10@3615,515
AD1: J1.11 U1.6 | length 1065.2
  Top Layer w10: U1.6@2959.5,85.6 3510.6,85.6 3715,290 J1.11@3715,515
AD2: J1.12 U1.5 | length 1333.2
  Top Layer w10: U1.5@2770.5,85.6 2899.4,85.6 2920,65 3525,65 3815,355 J1.12@3815,515
AD3: J1.13 U1.4 | length 1502.5
  Top Layer w10: U1.4@2770.5,105.3 2745.3,105.3 2735,95 2735,75 2745,65 2890,65 2910,45 3540,45 3915,420 J1.13@3915,515
DA0: C5.2 C9.1 J1.8 U3.6 U3.7 | length 3019.7
  Top Layer w15: C5.2@914.68,155 C9.1@990,155 ; U3.6@970,268.54 U3.6@970,270 ; v1(970,345) U3.6@970,270 ; C9.1@991.54,155 991.54,191.54 1020,220 U3.7@1020,268.54 1020,270 U3.6@970,270
  INT2 w10: v1(970,345) 970,395 995,420 1590,420 1735,275 2375,275 2552,452 3397,452 3415,470 J1.8@3415,515
DA1: C4.2 C8.2 J1.9 U3.1 U3.2 | length 2986.4
  Top Layer w15: C4.2@914.68,575 990,575 990,535 1023.54,501.46 1023.54,461.46 U3.1@1070,461.46 ; v1(1020,385) U3.2@1020,461.46
  INT2 w10: v1(1020,385) 1590,385 1725,250 2385,250 2565,430 3405,430 3490,515 J1.9@3515,515
GND: C1.2 C2.2 C3.1 C6.1 C7.1 C10.2 C11.2 C12.2 C13.2 C14.2 C15.2 C16.1 C17.1 C18.1 C19.1 C20.1 C21.1 C22.1 C23.1 C24.1 C25.1 C26.1 D1.2 D2.2 D3.2 D4.2 J1.1 J1.2 J1.3 J1.4 J1.5 J1.6 J1.7 J7.10 J8.1 J9.1 J10.5 J10.6 J12.5 J12.6 J13.- J14.6 J14.13 J15.5 J15.6 MTG1.1 MTG2.1 MTG3.1 MTG4.1 Q2.2 Q4.2 Q5.2 Q6.2 R1.5 R1.8 R11.1 R12.1 R13.1 R21.8 SW1.2@2191.5,556.42 U1.3 U2.2 U3.4 U4.3 U5.3 U6.2 U7.1 U7.2 U7.4 U7.7 U8.5 U8.6 U8.17 U8.27 U8.39 U9.6 U9.16 VR1.3 VR2.1 | length 1386.1
  Top Layer w7: v1@819.65,930.35 U4.3@819.65,969.41 ; C2.2@2705,95 C2.2@2705,96.38 2705,100 2730,125 U1.3@2770.5,125
  Top Layer w10: U9.16@602.8,872.2 602.8,927.8 655,980 v1(670,980) ; v1(1105,1365) C20.1@1105,1410 ; v1(1135,2195) v1@1135,2205 ; v1@1135.32,2194.68 R13.1@1175,2194.68 ; U7.1@1173.39,1312 1173.39,1383.39 1182.8,1392.8 1197.8,1392.8 ; U7.2@1197.8,1312 1197.8,1392.8 ; U7.7@1197.8,1538 1197.8,1492.67 1235.46,1455 1280,1455 v1(1295,1440) ; v1@1245,1395 1242.8,1392.8 1197.8,1392.8 ; U7.4@1246.61,1312 v1@1246.61,1383.39 ; Q5.2@1307.5,2136.25 1307.5,2097.5 v1(1315,2090) ; U8.6@1360,1425 1310,1425 v1(1295,1440) ; U8.5@1360,1456.5 1311.5,1456.5 v1(1295,1440) ; U5.3@1491.61,2475.59 v1@1491.61,2515 ; C21.1@1543.62,1730 1585,1730 v1(1590,1725) 1585,1725 U8.39@1585,1650 ; C18.1@1575.32,1110 1575.32,1150.32 1585,1160 U8.17@1585,1200 ; v1@1746.5,1393.5 U8.27@1810,1393.5 ; v1(2705,50) C2.2@2705,95
  other v1: 2095,205 590,210 3465,220 1510,295 775,365 355,415 200,430 875,465 2130,625 550,635 600,670 340,825 210,925 820,930 535,1025 1530,1115 1855,1220 310,1255 1246.61,1393.39 1745,1395 1785,1650 1305,1925 1910,1990 2250,2080 160,2170 2250,2170 555,2315 1440,2345 1175,2360 1287.5,2440 1490,2530 1750,2535 1840,2535 2190,2655 2240,2655 2290,2655 2340,2655 2390,2655 1885,2715 2190,2715 2190,2770 2190,2825 2190,2875 2190,2935 2240,2935 2290,2935 2340,2935 2390,2935 1835,2955
  other v2: 2225,2545 2300,2545 2380,2545 2190,2605 2265,2605 2340,2605 2415,2605
NetC4_1: C4.1 R3.1 R5.2 | length 184.5
  Top Layer w10: R3.1@765,545 765.32,544.68 R5.2@815,544.68 864.68,544.68 875.32,555.32 C4.1@875.32,575 ; R3.1@765,548.62 R5.2@815,548.62
NetC5_1: C5.1 R4.1 R6.2 | length 113.9
  Top Layer w10: R4.1@765,190 765.32,190.32 R6.2@815,190.32 ; R6.2@820,185 850,155 C5.1@871.38,155
NetC6_2: C6.2 R5.1 U3.3 | length 303.6
  Top Layer w10: R5.1@815,505 C6.2@815,439.68 845.32,439.68 895,390 955,390 970,405 U3.3@970,461.46
NetC7_2: C7.2 R6.1 U3.5 | length 181.1
  Top Layer w10: R6.1@815,229.68 839.68,229.68 878.54,268.54 U3.5@920,268.54 ; R6.1@815,235 C7.2@815,295
NetC8_1: C8.1 J9.3 | length 403.1
  Top Layer w25: C8.1@1050,575 C8.1@1058.46,575 1115,575 1219,471 J9.3@1219,286 ; J9.3@1220,280 J9.3@1220,286
NetC9_2: C9.2 J9.2 | length 1095.9
  Top Layer w25: C9.2@1058.46,155 1170,155 1220,105 1575,105 1600,130 1600,555 1580,575 J9.2@1510,575
NetC22_2: C22.2 FB2.2 J8.5 | length 277.9
  Top Layer w15: J8.5@281.42,1053 323,1053 362.24,1092.24 C22.2@362.24,1205 ; C22.2@365,1205 FB2.2@433.07,1205
NetC24_2: C24.2 J8.3 R19.2 | length 371.4
  Top Layer w15: J8.3@281.42,990 345,990 400,935 400,775 ; C24.2@365,775 400,775 ; R19.2@435,775 400,775
NetC25_2: C25.2 J8.4 R18.2 | length 652
  Top Layer w10: v1(385,670) 437.5,670 ; C25.2@437.5,637.5 437.5,670 ; R18.2@437.5,705 437.5,670
  Top Layer w15: J8.4@281.42,1021.5 438.5,1021.5 v1(440,1020)
  INT2 w10: v1(385,670) 440,725 v1(440,1020)
NetC26_2: C26.2 U9.3 U9.13 U9.14 | length 465.4
  Top Layer w10: 550,925 535,925 526.02,916.02 U9.13@526.02,872.2 526.02,838.98 565,800 C26.2@565,772.5 ; U9.14@551.61,872.2 551.61,946.61 653.98,1048.98 U9.3@653.98,1107.8
NetC28_1: C28.1 Q4.1 R21.1 | length 1069
  Top Layer w10: R21.1@220,465 255,465 v1(260,460) 262.4,457.6 Q4.1@304.41,457.6 ; v1(755,1160) 760,1165 760,1197.5 C28.1@767.5,1205
  INT2 w10: v1(260,460) 305,460 705,860 705,1110 v1(755,1160)
NetC28_2: C28.2 U9.1 | length 97.2
  Top Layer w10: U9.1@705.16,1107.8 C28.2@705.16,1205
NetD1_1: D1.1 R2.1 | length 3460
  Top Layer w10: R2.1@675,495 v1(720,495) ; D1.1@3573.46,270 3610,270 v1(3630,290)
  INT2 w10: v1(720,495) 785,495 815,465 815,205 975,45 2625,45 2695,115 3205,115 3380,290 v1(3630,290)
NetD2_1: D2.1 R2.4 | length 3167.6
  Top Layer w10: R2.4@675,555 v1(720,555) ; v1(3300,290) 3320,270 D2.1@3356.54,270
  INT2 w10: v1(720,555) 755,555 840,470 840,210 985,65 2615,65 2685,135 3195,135 3300,240 v1(3300,290)
NetD3_1: D3.1 R17.5 | length 298.4
  Top Layer w7: 2125,115 2205,115
  Top Layer w10: D3.1@2020,81.54 2066.54,81.54 2100,115 2125,115 ; 2205,115 2240,150 R17.5@2290,150
NetD4_1: D4.1 R17.8 | length 128.5
  Top Layer w10: D4.1@2165,81.54 2231.54,81.54 2240,90 R17.8@2290,90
